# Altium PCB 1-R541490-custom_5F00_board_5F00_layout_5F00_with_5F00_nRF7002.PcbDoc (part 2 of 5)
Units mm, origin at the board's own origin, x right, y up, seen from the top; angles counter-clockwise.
Board outline 180 x 80 mm, 6 copper layers (Top Layer, GND 1, Signal 1, POWER, GND 2, Bottom Layer), stack 1.609 mm thick; 321 components, 275 nets, 828 pads, 1164 vias.
Unrouted connection lines stored in the file: 746.
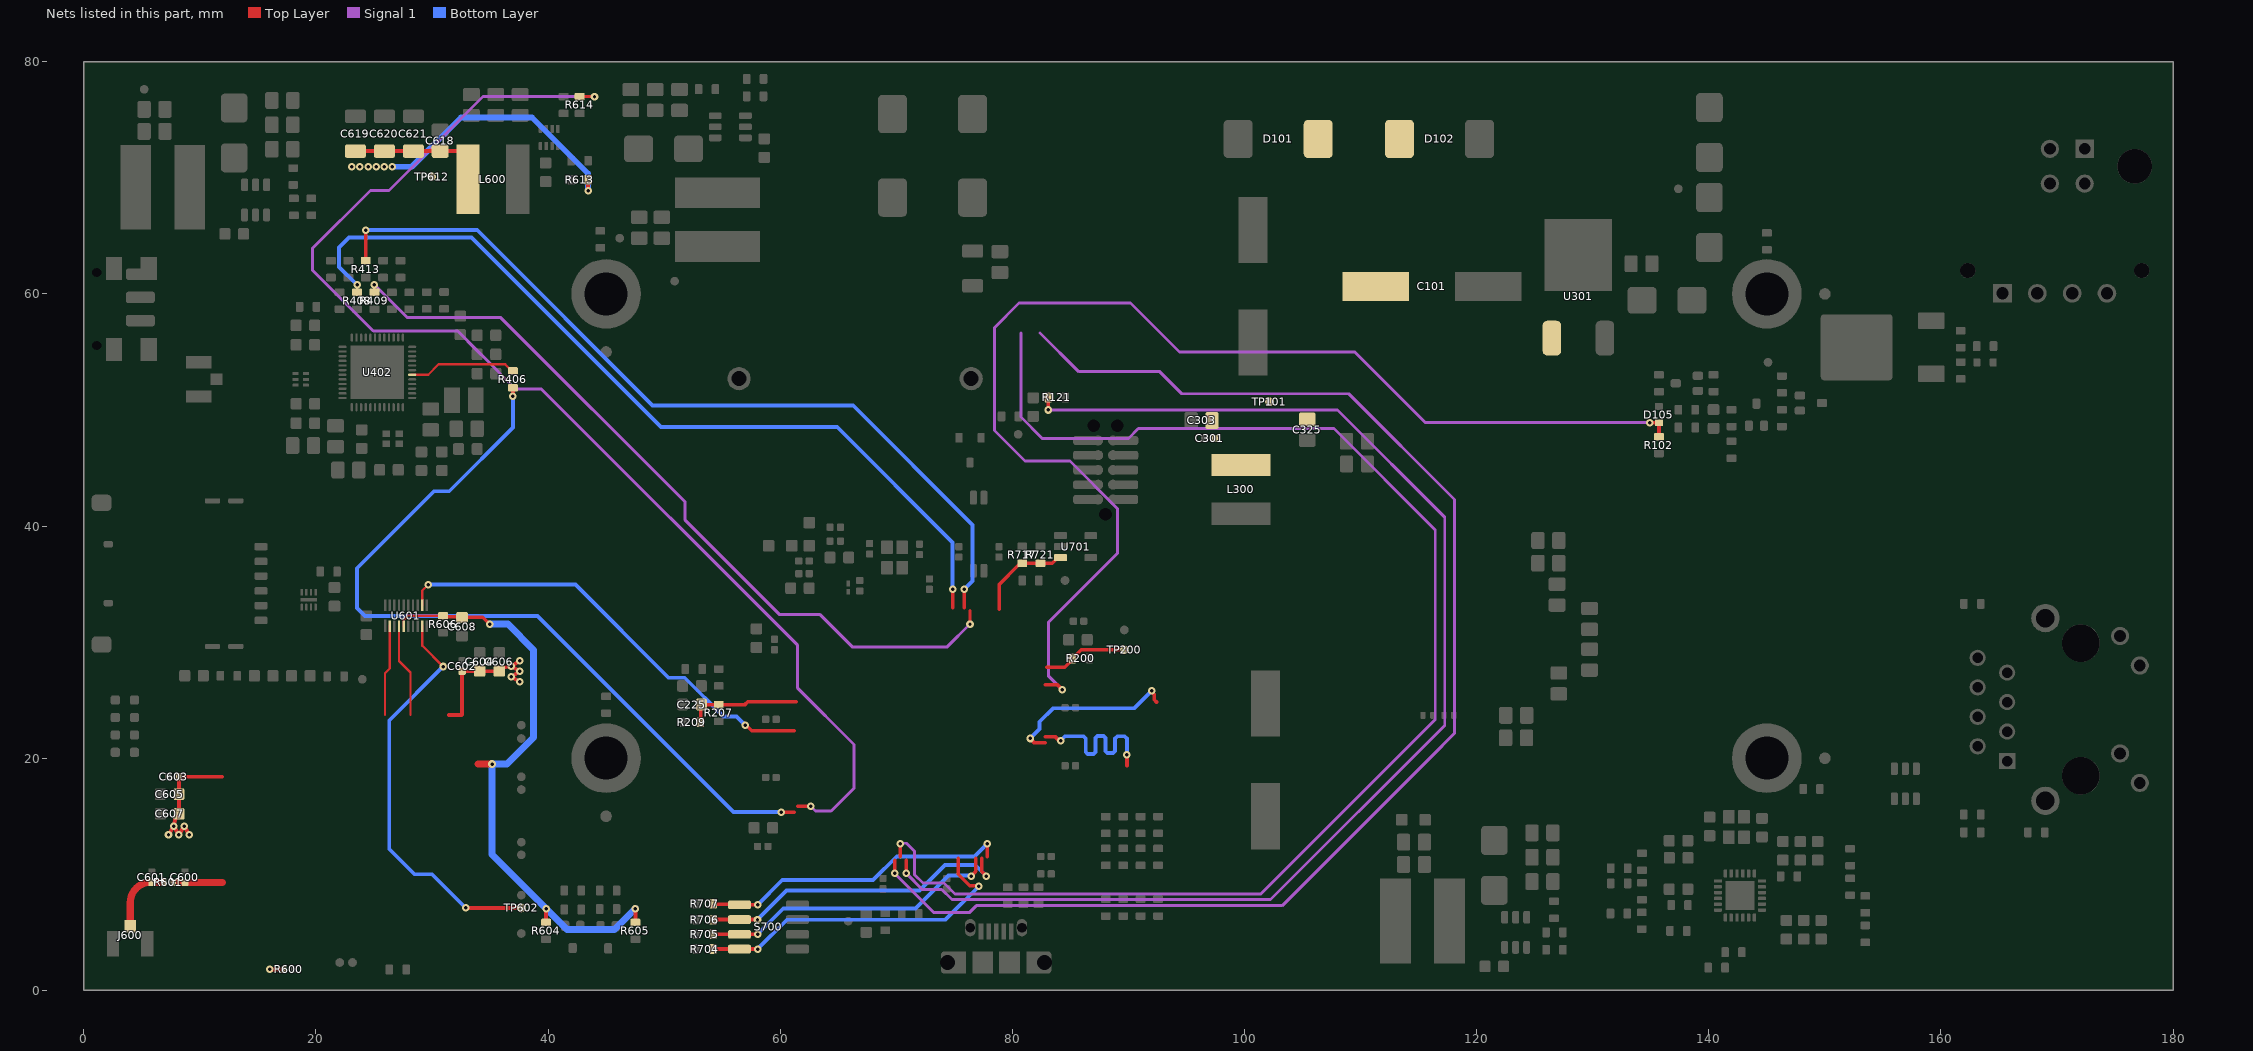
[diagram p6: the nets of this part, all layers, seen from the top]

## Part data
BT200: library part CMP-POW-BAT-00020-3, "BATTERY HOLDER CR 2032", Manufacturer 1="Adam Equipment"
C100 C101 C302: library part CMP-CAP-ALU-00015-7, "CAP ALUM 470UF 20% 50V SMD", Case/Package=Radial, Manufacturer 1="United Chemi-Con", Ripple Current=740mA, Tolerance=20%, Voltage Rating=50V
C102: library part CMP-CAP-CER-00205-11, "CAP CER 4.7UF 50V X7R 1206", Case/Package=1206, Dielectric=X7R, Manufacturer 1=Murata, Tolerance=10%, Voltage Rating=50V
C103 C303 C306 C308 C309 C318 C325 C403 C514 C617 C618 C704: library part CMP-CAP-CER-00029-14, "Multilayer Ceramic Capacitor, 0.1 uF, 50 V, ï¿½ 10%, X7R, 0805 [2012 Metric]", Case/Package=0805, Dielectric=X7R, Manufacturer 1=YAGEO, Tolerance=10%, Voltage Rating=50V
C113: library part CMP-CAP-CER-00092-13, "CAP CER 10UF 16V X5R 0603", Case/Package=0603, Dielectric=X5R, Manufacturer 1=Murata, Tolerance=10%, Voltage Rating=10V
C200 C206 C406 C408 C410 C421: library part CMP-CAP-CER-00144-13, "CAP CER 2.2UF 10V X7R 0603", Case/Package=0603, Dielectric=X7R, Manufacturer 1=Samsung, Tolerance=±10%, Voltage Rating=10V
C201 C203: library part CMP-CAP-CER-00179-16, "CAP CER 3.3PF 50V C0G/NP0 0402", Manufacturer 1=Murata, Tolerance=±0.05pF
C202 C220 C226: library part CMP-CAP-CER-00130-16, "CAP CER 1UF 16V X5R 0402", Manufacturer 1="Taiyo Yuden", Tolerance=10%
C204 C205: library part CMP-CAP-CER-00295-1, "Multilayer Ceramic Capacitor, 2.7 pF, 50 V, ï¿½ 0.25pF, C0G (NP0), 0402 [1005 Metric]", Manufacturer 1=YAGEO
C207 C223 C224 C225 C400 C407 C416 C502 C503 C504 C505 C506 C507 C508 C511 C604 C605 C608 C609 C614 C700: library part CMP-CAP-CER-00027-13, "CAP CER 0.1UF 50V X7R 0603", Case/Package=0603, Dielectric=X7R, Manufacturer 1=Murata, Tolerance=±10%, Voltage Rating=50V
C208: library part CMP-CAP-CER-00202-15, "CAP CER 4.7UF 16V X5R 0402", Manufacturer 1=Samsung, Tolerance=±20%
C209 C210 C211 C212 C213 C214 C215 C216 C217 C218 C219 C221 C227: library part CMP-CAP-CER-00025-17, "CAP CER 0.1UF 50V X7R 0402", Manufacturer 1=Murata, Tolerance=±20%
C222 C228 C414 C701: library part CMP-CAP-CER-00261-3, "0603 10 nF 50 V ±20% Tolerance X7R SMT Multilayer Ceramic Capacitor", Case/Package=0603, Dielectric=X7R, Manufacturer 1=Yageo, Tolerance=20%, Voltage Rating=50V
C301: library part CMP-CAP-CER-00157-17, "CAP CER 2200PF 50V X7R 0402", Manufacturer 1=Yageo, Tolerance=±5%
C304 C305 C307 C312 C313 C317 C321 C401 C402 C512 C513 C615 C616 C702 C703: library part CMP-CAP-CER-00135-12, "CAP CER 1UF 50V X7R 0805", Manufacturer 1=Samsung, Tolerance=±10%, Voltage Rating=50V
C404 C405 C411 C412 C417 C418 C515 C516 C705 C706: library part CMP-CAP-CER-00204-11, "CAP CER 4.7UF 16V X7R 0805", Case/Package=0805, Dielectric=X7R, Manufacturer 1=Murata, Tolerance=±10%, Voltage Rating=16V
C409 C422 C423 C501 C613: library part CMP-CAP-CER-00132-13, "CL10B105KA8NNNC Samsung Ceramic Capacitor MLCC 1uF10% 25V X7R SMD 0603 (1608 Metric) RoHS", Case/Package=0603, Dielectric=X7R, Manufacturer 1="Samsung Electro-Mechanics", Tolerance=10%, Voltage Rating=25V
C413 C415: library part CMP-CAP-CER-00043-13, "CAP CER 0.47UF 50V X5R 0603", Case/Package=0603, Dielectric=X5R, Manufacturer 1=Samsung, Tolerance=±10%, Voltage Rating=50V
C419: library part CMP-CAP-CER-00007-13, "CAP CER 0.022UF 50V X7R 0805", Case/Package=0805, Dielectric=X7R, Manufacturer 1=Yageo, Tolerance=±10%, Voltage Rating=50V
C420: library part CMP-CAP-CER-00035-13, "CAP CER 0.22UF 16V X7R 0603", Case/Package=0603, Dielectric=X7R, Manufacturer 1=KEMET, Tolerance=±10%, Voltage Rating=16V
C500: library part CMP-CAP-CER-00212-11, "CAP CER 470 PF 50V X7R 0603 PB T", Case/Package=0603, Dielectric=X7R, Manufacturer 1=Vishay, Tolerance=±10%, Voltage Rating=50V
C509 C510 C610 C611 C612: library part CMP-CAP-CER-00161-12, "CAP CER 22PF 50V C0G/NP0 0603", Case/Package=0603, Dielectric="C0G, NP0", Manufacturer 1="Kyocera AVX", Tolerance=±5%, Voltage Rating=50V
C600 C601: library part CMP-CAP-00000-5, "SMD capacitor", Manufacturer 1=TBD
C602 C603: library part CMP-CAP-CER-00195-16, "CAP CER 39PF 50V C0G/NP0 0402", Case/Package=0402, Dielectric="C0G, NP0", Manufacturer 1=KEMET, Tolerance=±5%, Voltage Rating=50V
C606 C607: library part CMP-CAP-CER-00165-12, "CAP CER 22UF 16V X5R 0603", Case/Package=0603, Dielectric=X5R, Manufacturer 1=Samsung, Tolerance=±20%, Voltage Rating=16V
C619 C620 C621: library part CMP-CAP-CER-00168-12, "CAP CER 22UF 16V X7R 1206", Case/Package=1206, Dielectric=X7R, Manufacturer 1="Taiyo Yuden", Tolerance=±20%, Voltage Rating=16V
D100 D104 D300 D400 D501 D704: library part CMP-DIO-SCH-00037-8, "DIODE SCHOTTKY 100V 2A SMA", Average Rectified Current=2A, Case/Package=DO-214AA, Forward Voltage=850mV, Manufacturer 1="Taiwan Semiconductor", Max Reverse Current=100µA, Max Reverse Voltage (DC)=100V
D101 D102 D103 D106: library part CMP-DIO-SCH-00038-7, "DIODE SCHOTTKY 40V 5A DO214AB", Average Rectified Current=5A, Case/Package=DO-214AB, Forward Voltage=550mV, Manufacturer 1=MCC, Max Reverse Current=1mA, Max Reverse Voltage (DC)=40V
D105 D107: library part CMP-DIO-RECT-00010-9, "DIODE GEN PURP 75V 200MA SOD523F", Average Rectified Current=200mA, Case/Package="SC-79, SOD-523", Forward Current=10mA, Forward Voltage=1V, Manufacturer 1="ON Semiconductor / Fairchild", Max Reverse Voltage (DC)=75V, Power Dissipation=200mW
D200: library part CMP-DIO-ARR-00002-8, "DIODE ARRAY SCHOTTKY 30V SOT23-3", Average Rectified Current=200mA, Case/Package="TO-236-3, SC-59, SOT-23-3", Forward Current=100mA, Forward Voltage=800mV, Manufacturer 1=Diodes, Max Reverse Current=2µA, Max Reverse Voltage (DC)=30V, Power Dissipation=200mW
D500: library part CMP-CPT-TVS-00084-1, "USBLC6 Series 4 Line 6 V Uni / Bi-Directional ESD Protection - SOT-23-6", Breakdown Voltage=6V, Case/Package=SOT-23, Clamping Voltage=17V, Leakage Current=150nA, Manufacturer 1=STMicroelectronics, Manufacturer Part Number 1=USBLC6-2SC6, Peak Pulse Current=5A, Power Line Protection=Yes, Reverse Standoff Voltage=5V
D700 D702: library part CMP-OPTE-LED-00052-3, "Led Red Diffused 0603 SMD", Case/Package=0603, Color=Red, Forward Voltage=2V, Manufacturer 1="Wurth Electronics"
D701 D703: library part CMP-OPTE-LED-00055-3, "Led Green Diffused 0603 SMD", Case/Package=0603, Color=Green, Forward Voltage=2V, Manufacturer 1="Wurth Electronics"
FB200 FB201 FB500: library part CMP-FIL-FB-00013-5, "FERRITE BEAD 600 OHM 0603 1LN", Case/Package=0603, Current Rating=700mA, Manufacturer 1="Taiyo Yuden", Tolerance=25%
FD1 FD2 FD3 FD4: library part CMP-MF-FID-00000-4
GS1: library part CMP-MF-SYM-00020-2
H5 H6 H7 H8: library part CMP-MF-MECH-00023-2, "Spacer Material: Steel Mounting: SMT Series: WA-SMSI Thread D: M2.5"
J100: library part CMP-CON-PCON-00000-3, "Header 2 Row Right-Angle Snap-In Lock 4Pin Tin Plate SMT/Glow Wire Compatible", Current Rating=8A, Manufacturer 1=Molex, Voltage Rating=600V
J101: library part CMP-CON-PCON-00010-2, "Connector Wire to Board Header 4 Position 3mm Solder Straight Thru-Hole Tray", Current Rating=5A, Insulation Resistance=1G, Manufacturer 1=Molex, Manufacturer Part Number 1=0436500415, Voltage Rating=600mV
J200: library part CMP-MF-NT-00002-1, "2 way net tie junction"
J201: library part CMP-CON-INF-00024-3, "CONN RCPT MICRO USB AB 5P SMD RA", Current Rating=1A, Manufacturer 1=Molex, Manufacturer Part Number 1=47589-0001, Max Voltage Rating (AC)=30V
J400 J600: library part CMP-2159-000000-3, "RF Connector; Coaxial Connectors MicroCoax receptacle UMCC Gen 1", Manufacturer 1="TE Connectivity AMP Connectors", Max Frequency=6GHz, Package=None
J500: library part CMP-CON-INF-00012-5, "CONN MAGJACK 1PORT 100BASE-T PCB", Manufacturer 1=WIZnet
J601: library part CMP-CON-MEM-00005-4, "CONN MICRO SIM CARD PUSH-PULL", Case/Package="Micro SIM", Manufacturer 1=Molex, Manufacturer Part Number 1=78646-3001
J700: library part CMP-CON-HEAD-00050-8, "CONN HEADER SMD 10POS 1.27MM", Current Rating=1A, Manufacturer 1="Amphenol ICC / FCI"
L300: library part CMP-IND-00075-10, "FIXED IND 3.3UH 4.95A 30 MOHM", Case/Package=Nonstandard, Current Rating=4.95A, DC Resistance (DCR)=23m, Manufacturer 1=TDK, Tolerance=30%
L400 L500 L700: library part CMP-IND-00067-9, "FIXED IND 22UH 1.2A 128 MOHM SMD", Case/Package=Nonstandard, Current Rating=1.2A, DC Resistance (DCR)=0.128, Manufacturer 1=Sumida, Tolerance=30%
L401: library part CMP-IND-00155-2, "Inductor Power Chip Shielded Multi-Layer 3.3uH 20% 1MHz Ferrite 1A 0.2Ohm DCR 1008 T/R", Case/Package=1008, Current Rating=1A, DC Resistance (DCR)=0.2, Manufacturer 1="Taiyo Yuden", Manufacturer Part Number 1=BRC2012T4R7MD, Self Resonant Frequency=30MHz, Tolerance=20%
L600: library part CMP-IND-00099-10, "FIXED IND 6.8UH 2.8A 47.3MOHM SM", Case/Package=Nonstandard, Current Rating=2.8A, DC Resistance (DCR)=47.3m, Manufacturer 1=Bourns, Self Resonant Frequency=20MHz, Tolerance=30%
Q100: library part CMP-TRN-FET-00089-1, "Trans MOSFET P-CH 40V 8.6A Automotive 3-Pin(2+Tab) DPAK T/R", Case/Package=TO-252-3, Continuous Drain Current (ID)=8.6A, Drain to Source Voltage (Vdss)=40V, Gate to Source Voltage (Vgs)=20V, Input Capacitance=1.643nF, Manufacturer 1="Diodes Incorporated"
Q101: library part CMP-TRN-BIP-00012-9, "TRANS PNP 45V 0.1A SOT-323", Case/Package="SC-70, SOT-323", Collector Emitter Breakdown Voltage=45V, Manufacturer 1="ON Semiconductor", Max Collector Current=100mA, Power Dissipation=150mW, Transition Frequency=100MHz
Q102 Q103 Q600 Q601: library part CMP-TRN-BIP-00007-7, "TRANS NPN 45V 0.1A SC70-3", Case/Package="SC-70, SOT-323", Collector Emitter Breakdown Voltage=45V, Manufacturer 1=Diodes, Max Collector Current=100mA, Power Dissipation=200mW, Transition Frequency=300MHz
R100 R106 R113 R117 R119 R123 R202 R401 R613 R615: library part CMP-RES-SMD-00313-9, "RES SMD 36K OHM 1% 1/10W 0603", Case/Package=0603, Manufacturer 1=Yageo, Temperature Coefficient=±100ppm/℃, Tolerance=1%
R102 R107 R112: library part CMP-RES-SMD-00223-9, "RES SMD 1K OHM 1% 1/10W 0603", Case/Package=0603, Manufacturer 1=Yageo, Temperature Coefficient=±100ppm/℃, Tolerance=1%
R108 R109 R110 R111 R402 R404 R405 R406 R407 R408 R409 R410 R411 R412 R413 R414 R415 R416 R515 R614: library part CMP-RES-SMD-00136-9, "RES SMD 0 OHM JUMPER 1/10W 0603", Case/Package=0603, Manufacturer 1=Yageo, Temperature Coefficient=±100ppm/℃, Tolerance=1%
R116 R120 R200 R208 R209 R403 R501 R502 R503 R510 R514 R520 R521 R603 R604 R605 R606 R607 R608 R609 R610 R611 R612 R616 R704 R705 R706 R707 R716 R717 R720 R721 R722: library part CMP-RES-SMD-00183-9, "RES SMD 10K OHM 1% 1/10W 0603", Case/Package=0603, Manufacturer 1=Yageo, Temperature Coefficient=±100ppm/℃, Tolerance=1%
R118: library part CMP-RES-SMD-00396-9, "RES SMD 680K OHM 1% 1/10W 0603", Case/Package=0603, Manufacturer 1=Yageo, Temperature Coefficient=±100ppm/℃, Tolerance=1%
R121 R518 R519: library part CMP-RES-SMD-00474-3, "Res Thick Film 0603 249 Ohm 1% 0.1W(1/10W) ±100ppm/°C Pad SMD T/R", Case/Package=0603, Manufacturer 1=Yageo, Power Rating=100mW, Temperature Coefficient=100ppm/°C, Tolerance=1%, Voltage Rating=50V
R201 R203 R500: library part CMP-RES-SMD-00543-2, "SMD Chip Resistor, 1.5 kOhm, ± 1%, 100 mW, 0603 [1608 Metric], Thick Film, General Purpose", Case/Package=0603, Manufacturer 1=Yageo, Power Rating=100mW, Temperature Coefficient=100ppm/°C, Tolerance=1%, Voltage Rating=50V
R204 R206 R207: library part CMP-RES-SMD-00114-12, "SMD Chip Resistor, 68 kOhm, ï¿½ 1%, 100 mW, 0603 [1608 Metric], Thick Film, General Purpose", Case/Package=0603, Manufacturer 1=Yageo, Power Rating=100mW, Temperature Coefficient=100ppm/°C, Tolerance=1%, Voltage Rating=50V
R205 R400 R516 R718: library part CMP-RES-SMD-00047-11, "RES 100K OHM 1% 1/10W 0603", Case/Package=0603, Manufacturer 1="Stackpole Electronics", Temperature Coefficient=±100ppm/℃, Tolerance=1%
R300 R301: library part CMP-RES-SMD-00334-12, "RES SMD 4.99K OHM 1% 1/16W 0402", Manufacturer 1=Yageo, Temperature Coefficient=±100ppm/℃
R504 R505 R506 R507 R602: library part CMP-RES-SMD-00353-9, "RES SMD 49.9 OHM 1% 1/10W 0603", Case/Package=0603, Manufacturer 1=Yageo, Temperature Coefficient=±100ppm/℃, Tolerance=1%
R508 R509 R511 R512: library part CMP-RES-SMD-00094-11, "RES 33 OHM 1% 1/10W 0603", Case/Package=0603, Manufacturer 1=Yageo, Temperature Coefficient=±100ppm/℃, Tolerance=1%
R513: library part CMP-RES-SMD-00194-9, "RES SMD 12.1K OHM 1% 1/10W 0603", Case/Package=0603, Manufacturer 1=Yageo, Temperature Coefficient=±100ppm/℃, Tolerance=1%
R517 R719: library part CMP-RES-SMD-00091-11, "RES 31.6K OHM 1% 1/10W 0603", Case/Package=0603, Manufacturer 1="Stackpole Electronics", Temperature Coefficient=±100ppm/℃, Tolerance=1%
R600 R601: library part CMP-RES-SMD-00137-12, "RES SMD 0 OHM JUMPER 1/16W 0402", Case/Package=0402, Manufacturer 1=Yageo, Temperature Coefficient=±100ppm/℃, Tolerance=1%
R700 R701 R702 R703 R708 R709 R710 R711 R712 R713 R714 R715: library part CMP-RES-SMD-00510-2, "SMD Chip Resistor, 330 Ohm, ± 1%, 100 mW, 0603 [1608 Metric], Thick Film, General Purpose", Case/Package=0603, Manufacturer 1=Yageo, Power Rating=100mW, Temperature Coefficient=100ppm/°C, Tolerance=1%, Voltage Rating=50V
S100: library part CMP-SW-TSW-00014-2, "SWITCH SLIDE SPDT 100MA 12V", Manufacturer 1="Nidec Copal"
S700: library part CMP-SW-TSW-00009-3, "SWITCH SLIDE DIP SPST 25MA 24V", Contact Current Rating=25mA, Manufacturer 1=CTS, Voltage Rating (DC)=24V
SW100: library part CMP-SW-BUT-00018-4, "SWITCH TACTILE SPST-NO 0.05A 12V", Manufacturer 1="Wurth Electronics"
TP100 TP101 TP102 TP200 TP201 TP202 TP203 TP204 TP400 TP600 TP601 TP602 TP603 TP604 TP605 TP606 TP607 TP608 TP609 TP610 TP611 TP612 TP700 TP701: library part CMP-MF-TP-00003-4, "Test point 0.75 mm"
U301: library part CMP-POW-VOLR-LIN-00028-1, "IC Reg Linear 12V 1.5A TO252-3", Case/Package=DPAK, Manufacturer 1="Nisshinbo Micro Devices Inc.", Min Input Voltage=35V
U400 U501 U700: library part CMP-POW-VOLR-SW-00041-4, "4.5-V to 60-V, 600-mA buck converter in ultra-small SOT23 package 6-SOT-23-THIN -40 to 125", Case/Package="SOT-23-6 Thin, TSOT-23-6", Manufacturer 1="Texas Instruments", Max Input Voltage=60V, Min Input Voltage=4V, Output Current=600mA, Switching Frequency=2.1MHz
U401: library part CMP-2155-000000-4, "Signal Conditioning 2.4GHz and 5GHz Diplexer", Manufacturer=Murata
U402: library part CMP-2155-000001-8, "Wi-fi Dual Band Companion chip", Case/Package="48-VFQFN Exposed Pad", Manufacturer="Nordic Semiconductor"
U500: library part CMP-IC-INF-00025-2, "Small Footprint Rmii 10/100 Ethernet Transceiver 24 QFN 4X4X0.9MM T/r Rohs Compliant: Yes", Case/Package=QFN, Manufacturer 1=Microchip, Max Supply Voltage=3.3V, Min Supply Voltage=1.8V
U601: library part CMP-IC-INF-00005-3, "8-Bit Bidirectional Voltage-Level Shifter with Auto Direction Sensing and +/-15-kV ESD Protect 20-USON -40 to 85", Case/Package=20-UFDFN, Manufacturer 1="Texas Instruments", Max Supply Voltage=5.5V, Min Supply Voltage=1.2V
U602: library part CMP-CPT-TVS-00069-5, "Diode TVS Quad Bi-Dir 5V 8-Pin SLP EP T/R", Case/Package=8-XFDFN, Leakage Current=500nA, Manufacturer 1=Semtech, Reverse Standoff Voltage=5V
U603: library part CMP-POW-VOLR-SW-00040-5, "3.8-V to 28-V Input, 3-A synchronous buck converter in SOT-583 package 8-SOT-5X3 -40 to 150", Case/Package=SOT-583, Manufacturer 1="Texas Instruments", Max Input Voltage=28V, Min Input Voltage=3.8V, Output Current=3A, Output Voltage=22V, Switching Frequency=500kHz
U701: library part CMP-IC-OTH-00008-2, "Processor Supervisor 1 Open Drain/Push-Pull Automotive 5-Pin SOT-23 T/R", Case/Package=SOT-23-5, Max Supply Voltage=5.5V, Min Supply Voltage=2.7V
Y200: library part CMP-CRaO-CR-00038-2, "Crystal 0.032768MHz ±20ppm (Tol) 12.5pF Flexural 65000Ohm 4-Pin SMD T/R", Case/Package=SMD/SMT, ESR (Equivalent Series Resistance)=65k, Frequency=32.768kHz, Frequency Tolerance=20ppm, Load Capacitance=12.5pF, Manufacturer 1="Citizen Finedevice Co Ltd", Manufacturer Part Number 1=CM13032768DZCT
Y201 Y500: library part CMP-CRaO-CR-00007-6, "CRYSTAL 25.0000MHZ 10PF SMD", ESR (Equivalent Series Resistance)=100, Frequency=25MHz, Frequency Stability=±20ppm, Load Capacitance=10pF, Manufacturer 1=Abracon
Y400: library part CMP-CRaO-CR-00034-2, "WE-XTAL Quartz Crystal 40MHz 8pF", Case/Package=SMD/SMT, ESR (Equivalent Series Resistance)=100, Frequency=40MHz, Frequency Stability=15ppm, Load Capacitance=8pF, Manufacturer 1="Würth Elektronik"

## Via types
v1: diameter 0.65, hole 0.3, Top Layer to Bottom Layer, tented both sides, 675 vias
v2: diameter 0.7, hole 0.3, Top Layer to Bottom Layer, tented both sides, 462 vias
v3: diameter 0.6, hole 0.3, Top Layer to Bottom Layer, 16 vias
v4: diameter 0.6, hole 0.3, Top Layer to Bottom Layer, tented both sides, 7 vias
v5: diameter 0.6, hole 0.3, Top Layer to Bottom Layer, tented bottom, 4 vias

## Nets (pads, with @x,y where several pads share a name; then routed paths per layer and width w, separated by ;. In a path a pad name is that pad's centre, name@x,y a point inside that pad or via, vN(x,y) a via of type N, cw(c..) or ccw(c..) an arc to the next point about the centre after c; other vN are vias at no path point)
+1.8V_modem: C608.1 R604.2 R605.2 R606.2 U601.5 | length 52.4
  Top Layer w0.2: U601.5@27.56,31.37 27.56,31.911 27.918,32.27 R606.2@30.96,32.27
  Top Layer w0.3: R606.2@30.96,32.27 31.035,32.195 32.511,32.195 C608.1@32.586,32.12 32.623,32.157 34.381,32.157 v1(34.994,31.545)
  Top Layer w0.335: R604.2@39.826,5.85 v1(39.826,7.046) ; R605.2@47.526,5.85 v1(47.526,7.046)
  Top Layer w0.6: 33.975,19.5 v1(35.171,19.5)
  Bottom Layer w0.6: v1(34.994,31.545) 36.539,31.545 38.75,29.334 38.75,21.773 36.477,19.5 v1(35.171,19.5) 35.171,11.701 v1(39.826,7.046) 41.622,5.25 45.73,5.25 v1(47.526,7.046)
+VCC__: C101.1 C301.2 C303.2 C325.2 D101.1 D102.1 L300.1 TP101.1 U301.1
+VCC_modem: C602.1 C603.2 C604.1 C605.2 C606.1 C607.2 C618.2 C619.2 C620.2 C621.2 L600.2 R600.2 R613.2 TP612.1 | length 60.2
  Top Layer w0.335: v1(7.3,13.4) v1(7.75,14.145) ; v1(9.1,13.4) v1(8.65,14.145) v1(8.2,13.4) v1(7.75,14.145) ; 11.925,18.4 C603.2@8.2,18.4 C607.2@8.2,15.2 7.892,14.868 v1(7.75,14.145) ; v1(16.029,1.8) R600.2@17.225,1.8 ; C619.2@23.4,72.3 C620.2@25.9,72.3 C621.2@28.4,72.3 C618.2@30.7,72.3 32.261,72.3 33.094,71.467 L600.2@33.094,69.876 ; 31.45,23.73 32.55,23.73 32.575,23.755 32.575,27.469 C602.1@32.6,27.494 32.603,27.497 35.797,27.497 C606.1@35.8,27.5 36.133,27.807 v1(36.83,27.93) ; v1(37.575,26.58) v1(36.83,27.03) v1(37.575,27.48) v1(36.83,27.93) ; v1(37.575,28.38) v1(36.83,27.93) ; v1(43.444,68.906) R613.2@43.444,69.836
  Bottom Layer w0.5: v1(26.594,70.956) 28.256,70.956 32.5,75.2 38.622,75.2 43.444,70.378 v1(43.444,68.906)
  other v1: 23.094,70.956 23.794,70.956 24.494,70.956 25.194,70.956 25.894,70.956
ACOK:  | length 120.5
  Top Layer w0.3: 70.35,11.501 v1(70.35,12.639)
  Signal 1 w0.256: v1@70.417,12.706 70.449,12.674 70.876,12.674 71.55,12 71.55,9.99 72.29,9.25 74.105,9.25 75.055,8.3 101.4,8.3 116.432,23.332 116.432,39.668 107.7,48.4 90.85,48.4 90,47.55 82.575,47.55 80.737,49.387 80.737,56.634
  Signal 1 w0.3: v1(70.35,12.639) v1@70.417,12.706
ANT_LTE_1: C600.2 R601.1 | length 4.1
  Top Layer w0.62: R601.1@7.82,9.3 C600.2@8.666,9.3 ; C600.2@8.716,9.3 11.925,9.3
ANT_LTE_2: C601.2 J600.1 R601.2 | length 5.8
  Top Layer w0.62: J600.1@4,5.525 4,7.553 cw(c5.747,7.553) 5.747,9.3 R601.2@6.78,9.3
AOutRf: 
AP_Rd: TP602.1 U601.9 | length 35.3
  Top Layer w0.2: U601.9@29.16,31.37 29.16,29.7 v1(30.96,27.9)
  Top Layer w0.335: v1(32.904,7.1) 33.975,7.1 TP602.1@37.7,7.1
  Bottom Layer w0.335: v1(30.96,27.9) 26.317,23.257 26.317,12.192 28.508,10 30.004,10 v1(32.904,7.1)
AP_REDY: U601.12 | length 38.8
  Top Layer w0.2: U601.12@29.16,33.17 29.16,34.44 v1(29.67,34.95)
  Top Layer w0.3: v1(56.968,22.85) 57.063,22.85 57.563,22.35 61.223,22.35
  Bottom Layer w0.335: v1(29.67,34.95) 42.35,34.95 50.369,26.931 51.776,26.931 55.107,23.6 56.218,23.6 v1(56.968,22.85)
"BAT voltage (ADC)": C225.2 R207.1 R209.2 | length 9.8
  Top Layer w0.3: R209.2@53.125,23.1 53.162,23.137 53.162,24.587 C225.2@53.2,24.625 56.968,24.625 57.193,24.85 61.362,24.85
BOOT: R200.2 TP200.1 | length 7.4
  Top Layer w0.3: 82.977,27.85 84.525,27.85 85.175,28.5 R200.2@85.175,28.6 85.925,29.35 89.182,29.35 TP200.1@89.65,29.35
BT_p: D105.2 R102.1 | length 106
  Top Layer w0.3: 82.838,26.35 83.85,26.35 v1(84.3,25.9)
  Top Layer w0.335: v1@134.901,48.9 D105.2@135.7,48.9 R102.1@135.7,47.699
  Signal 1 w0.256: v1(84.3,25.9) 83.1,27.1 83.1,31.7 89.043,37.644 89.043,41.518 84.961,45.6 81.097,45.6 78.456,48.24 78.456,57.09 80.58,59.214 90.186,59.214 94.4,55 109.5,55 115.597,48.903 v1(134.899,48.903)
BUCK_EN: R406.2 | length 70.3
  Top Layer w0.3: v1(60.085,15.35) 61.223,15.35
  Top Layer w0.335: v1@36.969,51.174 R406.2@36.969,51.912
  Bottom Layer w0.335: v1(36.967,51.173) 36.967,48.477 31.49,43 30.188,43 23.55,36.362 23.55,32.934 24.234,32.25 39.082,32.25 55.982,15.35 v1(60.085,15.35)
BUCK_EN_: R406.1 U402.30 | length 9.3
  Top Layer w0.2: U402.30@28.294,53.037 29.671,53.037 30.566,53.933 36.298,53.933 36.869,53.362 R406.1@36.969,53.362
CHGEN: R121.1 | length 111.7
  Top Layer w0.3: v1(70.85,10.085) 70.85,11.223 ; v1(83.1,50) R121.1@83.1,51.082
  Signal 1 w0.256: v1(70.85,10.085) 72.235,8.7 73.911,8.7 74.793,7.818 102.247,7.818 117.25,22.821 117.25,40.75 108,50 v1(83.1,50)
CHGOK:  | length 119
  Top Layer w0.3: v1(69.85,10.085) 69.85,11.223
  Signal 1 w0.256: v1(69.85,10.085) 73.242,6.693 76.293,6.693 76.896,7.296 103.249,7.296 116.04,20.086 118.1,22.147 118.1,42.282 108.982,51.4 94.6,51.4 92.7,53.3 85.721,53.3 82.387,56.634
CLK:  | length 14.9
  Top Layer w0.3: 82.838,21.85 83.701,21.85 83.719,21.833
  Top Layer w0.335: 83.719,21.833 83.894,21.657 83.907,21.657 84.065,21.5 v1(84.15,21.5) ; 89.865,19.35 v1@89.865,20.28
  Bottom Layer w0.335: v1(84.15,21.5) 84.546,21.896 85.114,21.896 86.125,21.896 86.321,21.7 86.321,20.52 86.49,20.351 86.995,20.351 87.164,20.52 87.164,21.735 87.333,21.904 87.838,21.904 88.007,21.735 88.007,20.625 88.176,20.456 88.681,20.456 88.85,20.625 88.85,21.7 89.046,21.896 89.214,21.896 89.667,21.896 89.863,21.7 v1(89.863,20.282)
COEX_GRANT: R408.2 | length 74.2
  Top Layer w0.2: R408.2@23.544,60.137 v1(23.544,60.787)
  Top Layer w0.3: 74.85,32.977 v1(74.85,34.55)
  Bottom Layer w0.335: v1(23.544,60.787) 22,62.331 22,64 22.85,64.85 33.408,64.85 49.733,48.525 64.916,48.525 74.85,38.591 v1(74.85,34.55)
COEX_REQ: R413.2 | length 72.9
  Top Layer w0.3: 75.85,32.977 v1(75.85,34.55)
  Top Layer w0.335: R413.2@24.294,62.862 24.297,62.866 24.297,65.497 v1(24.3,65.5)
  Bottom Layer w0.335: v1(24.3,65.5) 33.9,65.5 49.013,50.387 66.296,50.387 76.575,40.109 76.575,35.275 v1(75.85,34.55)
COEX_STATUS: R409.2 | length 67.7
  Top Layer w0.2: R409.2@25.044,60.137 v1(25.044,60.787)
  Top Layer w0.3: v1(76.35,31.561) 76.35,32.699
  Signal 1 w0.256: v1(25.044,60.787) 27.881,57.95 35.93,57.95 51.808,42.072 51.808,40.503 59.911,32.4 63.4,32.4 66.2,29.6 74.389,29.6 v1(76.35,31.561)
CS:  | length 15.1
  Top Layer w0.3: 81.876,21.367 81.894,21.35 82.838,21.35
  Top Layer w0.335: v1(81.526,21.7) 81.544,21.7 81.876,21.367 ; v1(91.99,25.8) 91.99,25.715 92.222,25.482 92.222,25.033 92.405,24.85
  Bottom Layer w0.335: v1(81.526,21.7) 82.339,22.513 82.339,23.139 83.5,24.3 90.49,24.3 v1(91.99,25.8)
CTS: U601.4 | length 8
  Top Layer w0.2: U601.4@27.16,31.37 27.16,28.365 28.15,27.375 28.15,23.73
DCD: U601.2 | length 7.8
  Top Layer w0.2: 25.95,23.73 25.95,27.325 26.36,27.735 U601.2@26.36,31.37
DipSw1: R707.1 S700.1 | length 27
  Top Layer w0.3: 77.85,11.501 v1(77.85,12.639)
  Top Layer w0.335: R707.1@54.258,7.415 S700.1@56.447,7.415 ; S700.1@56.49,7.372 v1@58.048,7.372
  Top Layer w0.4: R707.1@54.215,7.458 R707.1@54.258,7.415 ; S700.1@56.447,7.415 S700.1@56.49,7.372
  Bottom Layer w0.335: v1(58.05,7.371) 60.179,9.5 68,9.5 70.038,11.538 76.749,11.538 v1(77.85,12.639)
DipSw2: R706.1 S700.2 | length 27.6
  Top Layer w0.3: 77.35,11.362 77.35,10.245 v1(77.75,9.845)
  Top Layer w0.335: R706.1@54.223,6.095 56.482,6.095 v1@58.041,6.095
  Top Layer w0.4: R706.1@54.215,6.087 R706.1@54.223,6.095 ; S700.2@56.482,6.095 S700.2@56.49,6.102
  Bottom Layer w0.335: v1(58.042,6.093) 60.557,8.607 72.015,8.607 74.198,10.79 76.805,10.79 v1(77.75,9.845)
DipSw3: R705.1 S700.3 | length 26
  Top Layer w0.3: v1(76.45,9.845) 76.85,10.245 76.85,11.362
  Top Layer w0.335: R705.1@54.217,4.835 S700.3@56.488,4.835 ; S700.3@56.49,4.832 v1@58.048,4.832
  Top Layer w0.4: R705.1@54.215,4.837 R705.1@54.217,4.835 ; S700.3@56.488,4.835 S700.3@56.49,4.832
  Bottom Layer w0.335: v1(58.05,4.831) 60.265,7.046 71.646,7.046 74.493,9.892 76.402,9.892 v1(76.45,9.845)
DipSw4: R704.1 S700.4 | length 28.7
  Top Layer w0.3: 75.35,11.362 75.35,9.997 76.325,9.022 77.033,9.022 v1(77.1,8.955)
  Top Layer w0.335: R704.1@54.215,3.562 S700.4@56.49,3.562 v1@58.048,3.562
  Bottom Layer w0.335: v1(58.05,3.561) 60.576,6.087 64.176,6.087 64.177,6.088 74.233,6.088 v1(77.1,8.955)
DTR: 
EN: R717.1 R721.2 U701.3 | length 8.4
  Top Layer w0.3: 78.85,32.838 78.85,34.96 80.515,36.625 80.675,36.625 80.854,36.804 R721.2@82.417,36.804 83.428,36.804 83.899,37.275 U701.3@84.149,37.275
EN_LTE_POW: R614.2 | length 108.2
  Top Layer w0.256: R614.2@42.719,77.001 v1(44,77.001)
  Top Layer w0.3: 61.501,15.85 v1(62.639,15.85)
  Signal 1 w0.256: v1(44,77.001) 34.401,77.001 26.306,68.906 24.692,68.906 19.694,63.908 19.694,62.05 24.944,56.8 32.212,56.8 33.899,55.114 33.899,55.111 34.252,54.758 34.254,54.758 37.2,51.812 39.414,51.812 61.5,29.726 61.5,26.036 66.35,21.186 66.35,17.407 64.393,15.45 63.039,15.45 v1(62.639,15.85)
FAULT: 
